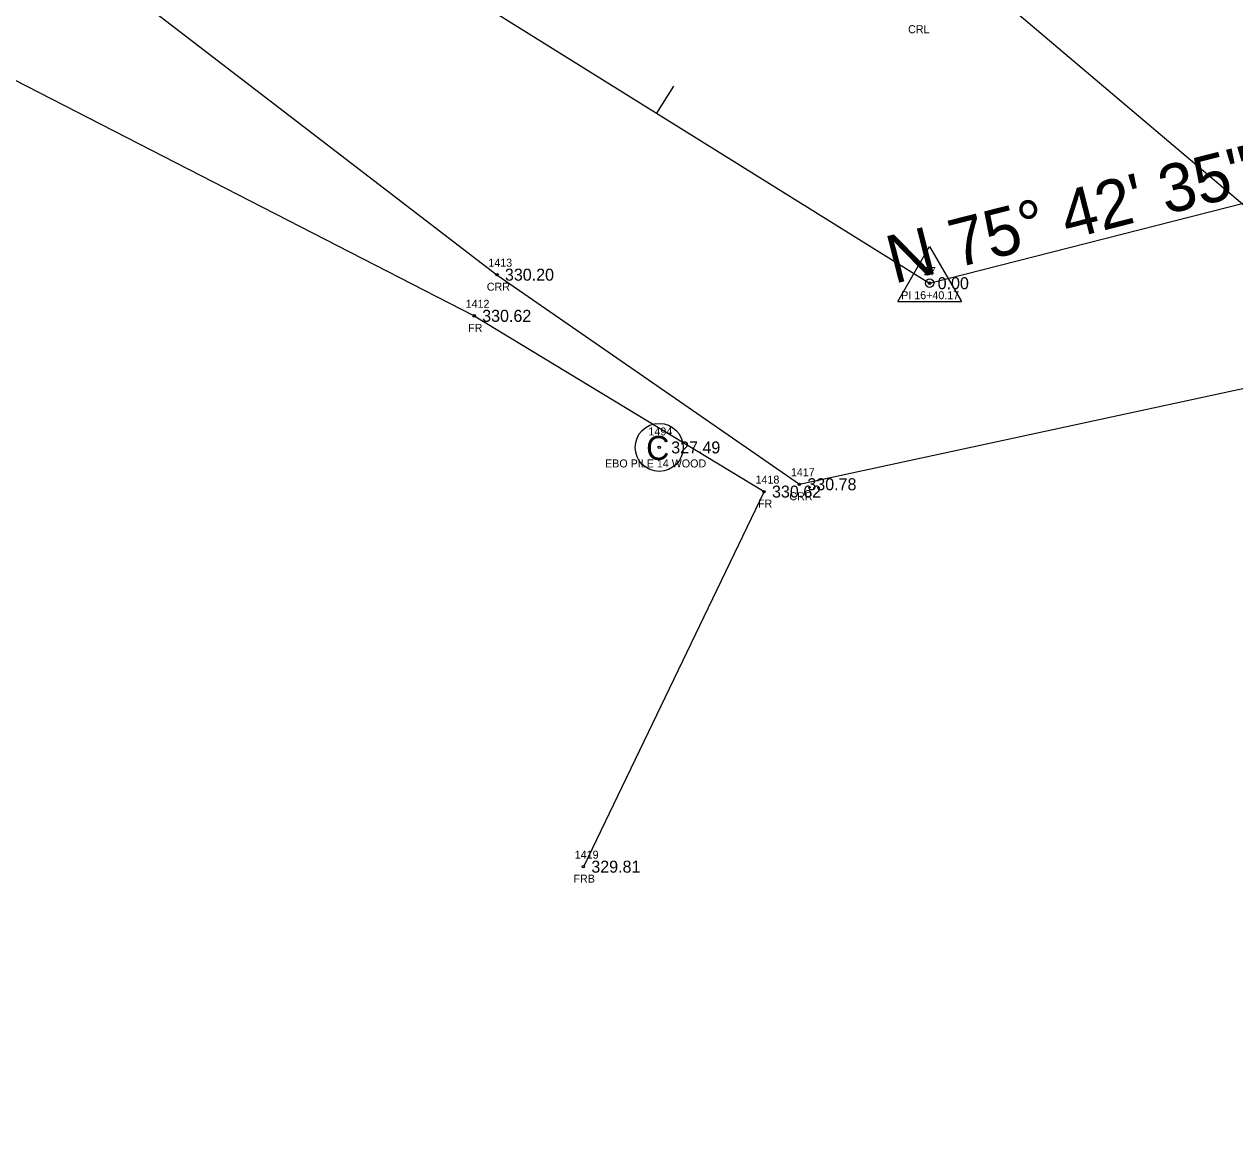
# Model space of a CAD drawing. Extents: x 2006517 to 2008868, y 1001613 to 1004633.
# Drawn here: x 2007680.3 to 2007831.6, y 1002790.5 to 1002930.6 of the extents above; entities that cross this region are included whole.
import ezdxf

# ---------------------------------------------------------------- set-up
doc = ezdxf.new("R2010")
doc.units = 0
for name, color, linetype in [('RD_EX_Bridge', 7, 'Continuous'), ('RD_EX_Bridge_txCode', 7, 'Continuous'), ('RD_EX_Fence_Other', 7, 'Continuous'), ('RD_EX_Fence_Other_txCode', 7, 'Continuous'), ('RD_EX_H2O', 7, 'Continuous'), ('RD_EX_H2O_txCode', 7, 'Continuous'), ('RD_EX_TX_Bridge_ELEV', 7, 'Continuous'), ('RD_EX_TX_Fence_Other_ELEV', 7, 'Continuous'), ('RD_EX_TX_H2O_ELEV', 7, 'Continuous'), ('RD_EX_VEG', 7, 'Continuous'), ('RD_HC_Cl', 7, 'Continuous'), ('RD_HC_Data', 7, 'Continuous'), ('RD_HC_Data_Tic', 7, 'Continuous'), ('RD_HC_Survey_ELEV', 7, 'Continuous'), ('RD_HC_txCode', 7, 'Continuous'), ('RD_SMD_Locator', 7, 'Continuous')]:
    doc.layers.add(name, color=color, linetype=linetype)

msp = doc.modelspace()

# ---------------------------------------------------------------- linework, layer by layer
at = {"layer": 'RD_EX_Bridge'}
msp.add_circle((2007759.65, 1002877.75), 3, dxfattribs=at)
at = {"layer": 'RD_EX_Fence_Other'}
msp.add_lwpolyline([(2007311.29, 1002972.59), (2007376.57, 1003048.27), (2007393.42, 1003067), (2007418.68, 1003075.73), (2007456.82, 1003064.75), (2007519.32, 1003029.04), (2007548.19, 1003007.7), (2007604.76, 1002975.57), (2007655.69, 1002935.71), (2007736.53, 1002894.19), (2007772.75, 1002872.23), (2007750.17, 1002825.37)], dxfattribs=at)
at = {"layer": 'RD_EX_H2O'}
msp.add_lwpolyline([(2007669.06, 1002953.29), (2007739.37, 1002899.33), (2007777.17, 1002873.15), (2007843, 1002887.34), (2007865.59, 1002908.46), (2007889.4, 1002933.96), (2007902.62, 1002951.59), (2007899.23, 1002956.7), (2007961.45, 1003046.31), (2007979.35, 1003079.78), (2008004.37, 1003099.33), (2008040.91, 1003092.79), (2008074.17, 1003079.43), (2008125.54, 1003053.8), (2008176.9, 1003027.12), (2008276.14, 1003020.76), (2008327.51, 1003029.06)], dxfattribs=at)
at = {"layer": 'RD_EX_VEG'}
msp.add_lwpolyline([(2007395.89, 1003327.12), (2007429.8, 1003285.17), (2007467.04, 1003247.92), (2007498.61, 1003210.85), (2007670.4, 1003045.37), (2007967.56, 1002793.96), (2008054.61, 1002736.66), (2008078.76, 1002693.39), (2008113.28, 1002661.09), (2008135.36, 1002619.06), (2008159.5, 1002583.06), (2008222.5, 1002503.36), (2008272.84, 1002426.91), (2008323.43, 1002347.7), (2008431.42, 1002192), (2008479.95, 1002108.23), (2008533.09, 1002033.28), (2008631.97, 1001873.89), (2008775.08, 1001653.06)], dxfattribs=at)
at = {"layer": 'RD_HC_Cl'}
for p, q in [((2007624.66, 1003003.39), (2007793.45, 1002898.27)), ((2007793.45, 1002898.27), (2007842.6, 1002910.79))]:
    msp.add_line(p, q, dxfattribs=at)
at = {"layer": 'RD_HC_Data'}
for p, q in [((2007789.48, 1002895.97), (2007793.45, 1002902.85)), ((2007793.45, 1002902.85), (2007797.42, 1002895.97)), ((2007789.48, 1002895.97), (2007797.42, 1002895.97))]:
    msp.add_line(p, q, dxfattribs=at)
msp.add_circle((2007793.45, 1002898.27), 0.529, dxfattribs=at)
at = {"layer": 'RD_HC_Data_Tic'}
msp.add_line((2007759.36, 1002919.5), (2007761.47, 1002922.9), dxfattribs=at)
at = {"layer": 'RD_SMD_Locator'}
for centre in [(2007739.37, 1002899.33), (2007793.45, 1002898.27), (2007736.53, 1002894.19), (2007759.65, 1002877.75), (2007777.17, 1002873.15), (2007772.75, 1002872.23), (2007750.17, 1002825.37)]:
    msp.add_circle(centre, 0.15, dxfattribs=at)

# ---------------------------------------------------------------- texts
at = {"layer": 'RD_EX_Bridge'}
msp.add_text('C', height=3, dxfattribs=at).set_placement((2007758.02, 1002876.19))
at = {"layer": 'RD_EX_Bridge_txCode'}
for s, p in [('1494', (2007758.31, 1002879.25)), ('EBO PILE 14 WOOD', (2007752.89, 1002875.25))]:
    msp.add_text(s, height=1, dxfattribs=at).set_placement(p)
at = {"layer": 'RD_EX_Fence_Other_txCode'}
for s, p in [('1412', (2007735.46, 1002895.19)), ('FR', (2007735.77, 1002892.19)), ('1418', (2007771.69, 1002873.23)), ('FR', (2007772, 1002870.23)), ('1419', (2007749.1, 1002826.37)), ('FRB', (2007748.94, 1002823.37))]:
    msp.add_text(s, height=1, dxfattribs=at).set_placement(p)
at = {"layer": 'RD_EX_H2O_txCode'}
for s, p in [('CRL', (2007790.76, 1002929.5)), ('1413', (2007738.3, 1002900.33)), ('CRR', (2007738.11, 1002897.33)), ('1417', (2007776.11, 1002874.15)), ('CRR', (2007775.92, 1002871.15))]:
    msp.add_text(s, height=1, dxfattribs=at).set_placement(p)
at = {"layer": 'RD_EX_TX_Bridge_ELEV'}
msp.add_text('327.49', height=1.5, dxfattribs=at).set_placement((2007761.15, 1002877))
at = {"layer": 'RD_EX_TX_Fence_Other_ELEV'}
for s, p in [('330.62', (2007737.53, 1002893.44)), ('330.62', (2007773.75, 1002871.48)), ('329.81', (2007751.17, 1002824.62))]:
    msp.add_text(s, height=1.5, dxfattribs=at).set_placement(p)
at = {"layer": 'RD_EX_TX_H2O_ELEV'}
for s, p in [('330.20', (2007740.37, 1002898.58)), ('330.78', (2007778.17, 1002872.4))]:
    msp.add_text(s, height=1.5, dxfattribs=at).set_placement(p)
at = {"layer": 'RD_HC_Data'}
msp.add_text('N 75%%d 42\' 35" E', height=6, rotation=14.2902, dxfattribs=at).set_placement((2007789, 1002898.17))
at = {"layer": 'RD_HC_Survey_ELEV'}
msp.add_text('0.00', height=1.5, dxfattribs=at).set_placement((2007794.45, 1002897.52))
at = {"layer": 'RD_HC_txCode'}
for s, p in [('27', (2007792.72, 1002899.27)), ('PI 16+40.17', (2007789.89, 1002896.27))]:
    msp.add_text(s, height=1, dxfattribs=at).set_placement(p)

doc.saveas('drawing.dxf')
